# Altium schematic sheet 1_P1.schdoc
size 309 x 223 mm; Symbol: Sheet-Symbol_A5; Device: Sheet-Symbol_A5; @Page Name: P1; @Create Date: 2023-12-07; @Page Count: 1; @Page No: 1; @Project Name: 树莓派pico_100M逻辑分析仪带IO保护; @Schematic Name: Schematic1; @Update Date: 2023-12-08; Company: 嘉立创EDA; Page Size: A5; Version: V1.0
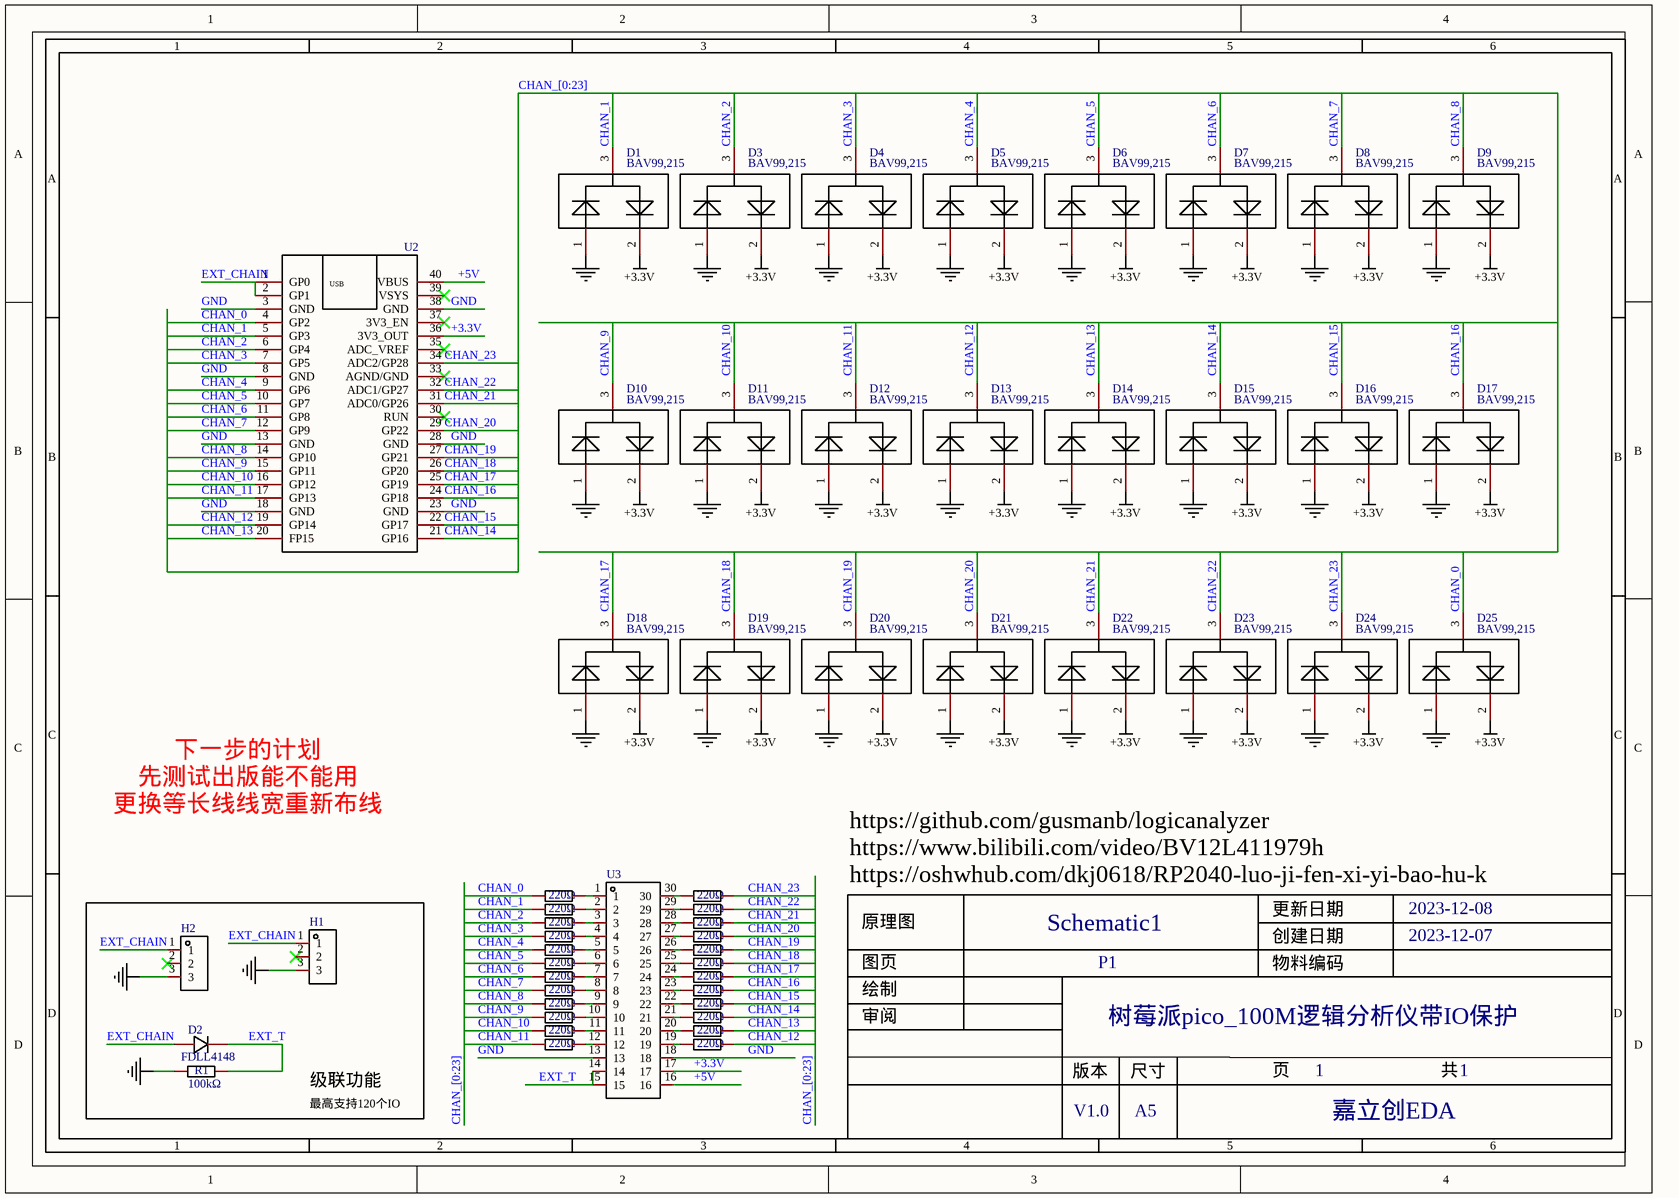
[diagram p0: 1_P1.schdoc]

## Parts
D1  BAV99,215  [SOT-23-3_L2.9-W1.6-P1.90-LS2.8-BR]
D2  FDLL4148  [SOD-80_L3.5-W1.5-RD]
D3  BAV99,215  [SOT-23-3_L2.9-W1.6-P1.90-LS2.8-BR]
D4  BAV99,215  [SOT-23-3_L2.9-W1.6-P1.90-LS2.8-BR]
D5  BAV99,215  [SOT-23-3_L2.9-W1.6-P1.90-LS2.8-BR]
D6  BAV99,215  [SOT-23-3_L2.9-W1.6-P1.90-LS2.8-BR]
D7  BAV99,215  [SOT-23-3_L2.9-W1.6-P1.90-LS2.8-BR]
D8  BAV99,215  [SOT-23-3_L2.9-W1.6-P1.90-LS2.8-BR]
D9  BAV99,215  [SOT-23-3_L2.9-W1.6-P1.90-LS2.8-BR]
D10  BAV99,215  [SOT-23-3_L2.9-W1.6-P1.90-LS2.8-BR]
D11  BAV99,215  [SOT-23-3_L2.9-W1.6-P1.90-LS2.8-BR]
D12  BAV99,215  [SOT-23-3_L2.9-W1.6-P1.90-LS2.8-BR]
D13  BAV99,215  [SOT-23-3_L2.9-W1.6-P1.90-LS2.8-BR]
D14  BAV99,215  [SOT-23-3_L2.9-W1.6-P1.90-LS2.8-BR]
D15  BAV99,215  [SOT-23-3_L2.9-W1.6-P1.90-LS2.8-BR]
D16  BAV99,215  [SOT-23-3_L2.9-W1.6-P1.90-LS2.8-BR]
D17  BAV99,215  [SOT-23-3_L2.9-W1.6-P1.90-LS2.8-BR]
D18  BAV99,215  [SOT-23-3_L2.9-W1.6-P1.90-LS2.8-BR]
D19  BAV99,215  [SOT-23-3_L2.9-W1.6-P1.90-LS2.8-BR]
D20  BAV99,215  [SOT-23-3_L2.9-W1.6-P1.90-LS2.8-BR]
D21  BAV99,215  [SOT-23-3_L2.9-W1.6-P1.90-LS2.8-BR]
D22  BAV99,215  [SOT-23-3_L2.9-W1.6-P1.90-LS2.8-BR]
D23  BAV99,215  [SOT-23-3_L2.9-W1.6-P1.90-LS2.8-BR]
D24  BAV99,215  [SOT-23-3_L2.9-W1.6-P1.90-LS2.8-BR]
D25  BAV99,215  [SOT-23-3_L2.9-W1.6-P1.90-LS2.8-BR]
H1  HDR-F_2.54_1x3P  [HDR-TH_3P-P2.54-V-F]  (value not drawn)
H2  HDR-M_2.54_1x3P  [HDR-TH_3P-P2.54-V-M]  (value not drawn)
R1  100kΩ  [R0603]
R2  220Ω  [R0603]
R3  220Ω  [R0603]
R4  220Ω  [R0603]
R5  220Ω  [R0603]
R6  220Ω  [R0603]
R7  220Ω  [R0603]
R8  220Ω  [R0603]
R9  220Ω  [R0603]
R10  220Ω  [R0603]
R11  220Ω  [R0603]
R12  220Ω  [R0603]
R13  220Ω  [R0603]
R14  220Ω  [R0603]
R15  220Ω  [R0603]
R16  220Ω  [R0603]
R17  220Ω  [R0603]
R18  220Ω  [R0603]
R19  220Ω  [R0603]
R20  220Ω  [R0603]
R21  220Ω  [R0603]
R22  220Ω  [R0603]
R23  220Ω  [R0603]
R24  220Ω  [R0603]
R25  220Ω  [R0603]
U2  树莓派pico  [树莓派pico多层]  (value not drawn)
U3  双排针母座2.54 2*15P  [HDR-TH_30P-P2.54-V-F-R2-C15-S2.54-A]  (value not drawn)

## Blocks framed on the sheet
级联功能: D2 H1 H2 R1

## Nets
+3.3V: D1.2 D3.2 D4.2 D5.2 D6.2 D7.2 D8.2 D9.2 D10.2 D11.2 D12.2 D13.2 D14.2 D15.2 D16.2 D17.2 D18.2 D19.2 D20.2 D21.2 D22.2 D23.2 D24.2 D25.2 U2.36(3V3_OUT) U3.17
NetD1_1: D1.1 D3.1 D4.1 D5.1 D6.1 D7.1 D8.1 D9.1 D10.1 D11.1 D12.1 D13.1 D14.1 D15.1 D16.1 D17.1 D18.1 D19.1 D20.1 D21.1 D22.1 D23.1 D24.1 D25.1 H1.3 H2.3 R1.1
+5V: U2.40(VBUS) U3.16
CHAN_0: D25.3 R2.1 U2.4(GP2)
CHAN_1: D1.3 R3.1 U2.5(GP3)
CHAN_2: D3.3 R4.1 U2.6(GP4)
CHAN_3: D4.3 R5.1 U2.7(GP5)
CHAN_4: D5.3 R6.1 U2.9(GP6)
CHAN_5: D6.3 R7.1 U2.10(GP7)
CHAN_6: D7.3 R8.1 U2.11(GP8)
CHAN_7: D8.3 R9.1 U2.12(GP9)
CHAN_8: D9.3 R10.1 U2.14(GP10)
CHAN_9: D10.3 R11.1 U2.15(GP11)
CHAN_10: D11.3 R12.1 U2.16(GP12)
CHAN_11: D12.3 R13.1 U2.17(GP13)
CHAN_12: D13.3 R25.2 U2.19(GP14)
CHAN_13: D14.3 R24.2 U2.20(FP15)
CHAN_14: D15.3 R23.2 U2.21(GP16)
CHAN_15: D16.3 R22.2 U2.22(GP17)
CHAN_16: D17.3 R21.2 U2.24(GP18)
CHAN_17: D18.3 R20.2 U2.25(GP19)
CHAN_18: D19.3 R19.2 U2.26(GP20)
CHAN_19: D20.3 R18.2 U2.27(GP21)
CHAN_20: D21.3 R17.2 U2.29(GP22)
CHAN_21: D22.3 R16.2 U2.31(ADC0/GP26)
CHAN_22: D23.3 R15.2 U2.32(ADC1/GP27)
CHAN_23: D24.3 R14.2 U2.34(ADC2/GP28)
EXT_CHAIN: D2.2(A) H1.1 H2.1 U2.1(GP0) U2.2(GP1)
EXT_T: D2.1(C) R1.2 U3.14 U3.15
GND: U2.3(GND) U2.8(GND) U2.13(GND) U2.18(GND) U2.23(GND) U2.28(GND) U2.38(GND) U3.13 U3.18
NetR2_2: R2.2 U3.1
NetR3_2: R3.2 U3.2
NetR4_2: R4.2 U3.3
NetR5_2: R5.2 U3.4
NetR6_2: R6.2 U3.5
NetR7_2: R7.2 U3.6
NetR8_2: R8.2 U3.7
NetR9_2: R9.2 U3.8
NetR10_2: R10.2 U3.9
NetR11_2: R11.2 U3.10
NetR12_2: R12.2 U3.11
NetR13_2: R13.2 U3.12
NetR14_1: R14.1 U3.30
NetR15_1: R15.1 U3.29
NetR16_1: R16.1 U3.28
NetR17_1: R17.1 U3.27
NetR18_1: R18.1 U3.26
NetR19_1: R19.1 U3.25
NetR20_1: R20.1 U3.24
NetR21_1: R21.1 U3.23
NetR22_1: R22.1 U3.22
NetR23_1: R23.1 U3.21
NetR24_1: R24.1 U3.20
NetR25_1: R25.1 U3.19

Not connected (* = marked no-connect by the designer): H1 2*; H2 2*; U2 30(RUN)* 33(AGND/GND)* 35(ADC_VREF)* 37(3V3_EN)* 39(VSYS)*

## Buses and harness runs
bus CHAN_[0:23]

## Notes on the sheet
- 下一步的计划
  先测试出版能不能用
  更换等长线线宽重新布线
- https://github.com/gusmanb/logicanalyzer
- https://www.bilibili.com/video/BV12L411979h
- https://oshwhub.com/dkj0618/RP2040-luo-ji-fen-xi-yi-bao-hu-k
- 最高支持120个IO

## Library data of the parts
D1 D3-D25 = BAV99,215: 二极管配置:1对串联式;正向压降(Vf):1.25V@150mA;直流反向耐压(Vr):100V;平均整流电流(Io):215mA;功率:250mW;反向恢复时间(trr):4ns;; Manufacturer: Nexperia(安世); Add into BOM: yes; Diode Configuration: 1对串联式; Reverse Voltage (Vr): 100V; Average Rectified Current (Io): 215mA; Power Dissipation: 250mW; Reverse Leakage Current: 500nA@80V; Reverse Recovery Time (trr): 4ns
D2 = FDLL4148: 二极管配置:-;正向压降(Vf):1V@10mA;直流反向耐压(Vr):100V;平均整流电流(Io):200mA;功率:-;反向恢复时间(trr):4ns;; Manufacturer: onsemi(安森美); Add into BOM: yes; Reverse Voltage (Vr): 100V; Average Rectified Current (Io): 200mA; Reverse Leakage Current: 5uA@75V; Reverse Recovery Time (trr): 4ns
H1 = HDR-F_2.54_1x3P: Manufacturer: XFCN(兴飞); Symbol: PM254V-11-03-H85; Convert to PCB: yes
H2 = HDR-M_2.54_1x3P: Symbol: PZ254V-11-03P_C2937625; Convert to PCB: yes
R1 = 0603WAF1003T5E: 阻值:100kΩ;精度:±1%;功率:100mW;温度系数:±100ppm/℃;电阻类型:厚膜电阻;; Manufacturer: UNI-ROYAL(厚声); Add into BOM: yes; Tolerance: ±1%; Power(Watts): 100mW; Overload Voltage (Max): 75V
R2-R25 = RC0603FR-07220RL: 电阻类型:厚膜电阻;阻值:220Ω;精度:±1%;功率:100mW;; Manufacturer: YAGEO(国巨); Add into BOM: yes; Tolerance: ±1%; Power(Watts): 100mW; Temperature Coefficient: ±100ppm/℃; Overload Voltage (Max): 75V
U2 = 树莓派pico: Add into BOM: yes
U3 = 双排针母座2.54 2*15P: Add into BOM: yes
